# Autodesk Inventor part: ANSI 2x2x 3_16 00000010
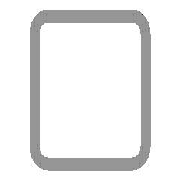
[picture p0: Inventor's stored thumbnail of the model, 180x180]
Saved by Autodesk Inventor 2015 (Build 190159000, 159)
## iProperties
IsCustomPart: 1
Created: 2007-02
Part Number: ANSI 2x2x 3_16 00000010
Material: Steel
Document SubType Name: Modeling
Standard: AISC
Designer: Autodesk, Inc.
Size Designation: 2x2x3/16
Stock Number: 2x2x 3/16
Density: 7.85 g/cm^3
Description: Tube
Standards Organization: ANSI
Language: en-US
Categories: <MemberInstance><Categories><Category DisplayName="Structural Shapes" InternalName="089c4875-fa83-4c05-b084-43b9cc11f5ed" Mnemonic="GRDR"><CategoryParameter Dis
Mass: 4523.85 g
Surface Area: 2436.47 cm^2
Volume: 576.287 cm^3
Appearance: Steel
_FrameMemberDoc: Frame Member File
_Version: 15.0.0
_CCFamilyMember: 1
_CCFamilyDisplayName: ANSI AISC (Square) - Tube
G_L: 27.716 in
G_W: 2.000 in
G_H: 2.000 in
+D4F599B4-B2A6-4265-AFE0-38A40571367F+CUTDETAIL1: Cut
Author: Autodesk, Inc.
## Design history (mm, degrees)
node "Start plane"
node "End plane"
sketch "Sketch"
  geometry: L1 (-25.4, -15.875)-(-25.4, 15.875); L2 (-15.875, 25.4)-(15.875, 25.4); L3 (25.4, 15.875)-(25.4, -15.875); L4 (15.875, -25.4)-(-15.875, -25.4); L5 (-15.875, 20.637)-(15.875, 20.638); L6 (20.637, 15.875)-(20.637, -15.875); L7 (15.875, -20.637)-(-15.875, -20.638); L8 (-20.637, -15.875)-(-20.637, 15.875); L9 (0, 38.322)-(0, -38.322) reference; L10 (-38.322, 0)-(38.322, 0) reference; A1 r 9.525 centre (-15.875, -15.875) between (-25.4, -15.875) and (-15.875, -25.4); A2 r 9.525 centre (-15.875, 15.875) between (-15.875, 25.4) and (-25.4, 15.875); A3 r 9.525 centre (15.875, 15.875) between (25.4, 15.875) and (15.875, 25.4); A4 r 9.525 centre (15.875, -15.875) between (15.875, -25.4) and (25.4, -15.875); A5 r 4.762 centre (-15.875, 15.875) between (-15.875, 20.637) and (-20.637, 15.875); A6 r 4.762 centre (15.875, 15.875) between (20.637, 15.875) and (15.875, 20.638); A7 r 4.762 centre (15.875, -15.875) between (15.875, -20.637) and (20.637, -15.875); A8 r 4.762 centre (-15.875, -15.875) between (-20.637, -15.875) and (-15.875, -20.638)
  constraints: 16 end point, 16 point on circle, 8 centre point, 8 tangent, 4 parallel, 3 equal radius, 2 perpendicular, 7 other
  dimensions: "d10" = 50.8 distance between parallel lines of L2 L4 (= G_H); "d11" = 50.8 distance between parallel lines of L1 L3 (= G_W); "d12" = 4.7625 distance between parallel lines of L3 L6 (= G_T); "d15" = 25.4 distance between parallel lines of L2 L10 (= 0.5 x d10); "d16" = 25.4 distance between parallel lines of L9 L3 (= 0.5 x d11); "d17" = 9.525 radius of A1 (= G_IR)
extrude "Body" new body sketch "Sketch" stored distance "d3" = 703.9864 (= G_L); taper "d4" = 0 deg
node "Driven Length"
  sketch "Sketch3"
    geometry: L1 (0, 0)-(10, 0) reference
    constraints: 2 end point, 1 horizontal
  workplane "Work Plane4"
  sketch "Sketch4"
    geometry: L1 (-2, 0)-(12, 0) reference; L2 (-2, 703.986)-(12, 703.986) reference
    dimensions: "d19" = 703.9864 distance between parallel lines of L1 L2 (derived)
workplane "Work Plane3"
split "Split1"
body "Solid1"
other parameters: "G_W" = 50.8 [user parameter; used in 1 equation term], "G_H" = 50.8 [user parameter; used in 1 equation term], "G_T" = 4.7625 [user parameter; used in 1 equation term], "G_IR" = 9.525 [user parameter; used in 1 equation term], "G_L" = 703.9864 (= d19) [user parameter; used in 1 equation term], "G_OFFSET_START" = 0 [user parameter; used in 1 equation term], "G_OFFSET_END" = -50.8 [user parameter; used in 1 equation term], "d13" = 0 (computed from G_OFFSET_START), "d14" = 703.9864 (= G_OFFSET_END + B_L), "B_L" = 754.7864 [user parameter; used in 1 equation term], "d18" = 90 deg
